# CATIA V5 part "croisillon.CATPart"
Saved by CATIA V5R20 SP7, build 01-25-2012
Part number: croisillon
Bounding box of the stored display mesh (mm): x -31 to 31, y -21.993 to 21.993, z -57.5 to 57.5
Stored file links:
  D:\thinkmotion-MPB\Dropbox\CIAO82010_JCF\SAINT-AIME\0558-SaintAime\CAO2\CAO\croisillon.CATPart
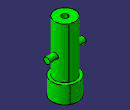
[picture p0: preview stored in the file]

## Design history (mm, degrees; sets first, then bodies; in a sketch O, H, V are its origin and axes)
Body1 (main body)
  Sketch1 on yz-plane, origin (0, 0, 0), H (0, 1, 0), V (0, 0, 1)
    point P1 (0, -57.5)
    line L1 (0, -57.5) -> (22, -57.5)
    line L2 (22, -57.5) -> (22, -28.75)
    line L3 (22, -28.75) -> (17, -28.75)
    line L4 (17, -28.75) -> (17, 57.5)
    line L5 (17, 57.5) -> (0, 57.5)
    point P6 (0, 57.5)
    line L6 (0, 57.5) -> (0, -57.5)
    distance L6 L4 = 17
    distance L2 L6 = 22
    distance L5 L1 = 115
    distance L3 L1 = 28.75
    coincidence: P1 V, P6 V
    horizontal: L1 H, L3 H, L5 H
    vertical: L2 V, L4 V, L6 V
    symmetry: L5 L1 H
  Shaft1: profile Sketch1, axis Sketch1.L6, angle 360
  Sketch2 on face of Shaft1 from Sketch1.L5, origin (0, 0, 57.5), H (1, 0, 0), V (0, 1, 0)
    circle A1 centre (0, 0) radius 5
    radius A1 = 5
  Pocket1: profile Sketch2, direction (0, 0, -1), through (limit type 3)
  Sketch3 on yz-plane, origin (0, 0, 0), H (0, 1, 0), V (0, 0, 1)
    circle A1 centre (0, 7.075) radius 5
    point P1 (0, 7.075)
    reference projected line E1 (35, -57.5) -> (-35, -57.5) from edge [face of Shaft1 from Sketch1.L2 | face of Shaft1 from Sketch1.L1]
    radius A1 = 5
    distance P1 E1 = 64.575
    distance V P1 = 0
  Pad1: profile Sketch3, direction (1, 0, 0), length 31, mirrored extent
